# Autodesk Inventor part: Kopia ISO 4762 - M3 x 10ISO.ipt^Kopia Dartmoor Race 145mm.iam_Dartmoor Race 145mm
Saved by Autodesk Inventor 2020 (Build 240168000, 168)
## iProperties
Created: 2017-10
Part Number: Kopia ISO 4762 - M3 x 10ISO.ipt^Kopia Dartmoor Race 145mm.iam_Dartmoor Race 145mm
Material: Ogólny
Document SubType Name: Modeling
Designer: Tomasz
Density: 1 g/cm^3
Appearance: Domyślna
Sending System: SolidWorks 2017
Last Author: Tomasz
Last Saved: 2017-10-01
Author: Tomasz
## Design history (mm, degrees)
